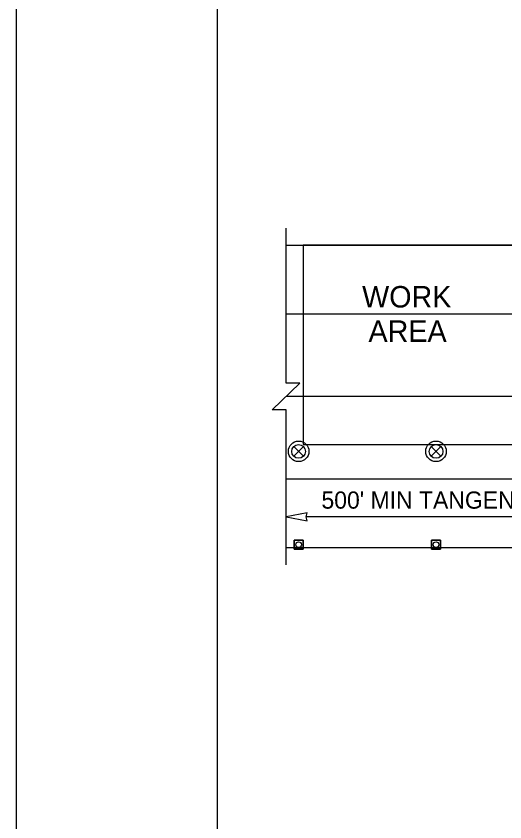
# Model space of a CAD drawing. Extents: x 99999 to 100116, y 99995 to 100013.
# Drawn here: x 100059.062 to 100061.34, y 100005.282 to 100009.035 of the extents above; entities that cross this region are included whole.
import ezdxf

# ---------------------------------------------------------------- set-up
doc = ezdxf.new("R2010")
doc.units = 0
for name, color, linetype in [('RD_MK_LineEdgeYellow', 7, 'Continuous'), ('RD_MK_LineLane', 7, 'Continuous'), ('SH_GI_PlotLimits', 7, 'Continuous'), ('SH_GI_SheetBorder', 7, 'Continuous'), ('TR_WZ_TrafficCone', 7, 'Continuous'), ('TR_WZ_TrafficSafetyDrum', 7, 'Continuous'), ('TR_WZ_WorkAreaLabel', 7, 'Continuous'), ('TR_WZ_WorkZoneDetails', 7, 'Continuous'), ('TR_WZ_WorkZoneTextCurrent', 7, 'Continuous')]:
    doc.layers.add(name, color=color, linetype=linetype)

msp = doc.modelspace()

# ---------------------------------------------------------------- linework, layer by layer
at = {"layer": 'RD_MK_LineEdgeYellow'}
for p, q in [((100060.32, 100007.648), (100062.7119, 100007.648)), ((100060.32, 100006.88), (100067.555, 100006.88))]:
    msp.add_line(p, q, dxfattribs=at)
at = {"layer": 'RD_MK_LineLane'}
msp.add_lwpolyline([(100067.555, 100007.264), (100060.32, 100007.264)], dxfattribs=at)
at = {"layer": 'SH_GI_PlotLimits'}
msp.add_lwpolyline([(100059.0625, 99999.6875), (100076.0625, 99999.6875), (100076.0625, 100010.6875), (100059.0625, 100010.6875)], close=True, dxfattribs=at)
at = {"layer": 'SH_GI_SheetBorder'}
msp.add_line((100060, 100010.375), (100060, 100000), dxfattribs=at)
at = {"layer": 'TR_WZ_TrafficCone'}
for points in [[(100060.3576, 100006.552), (100060.4003, 100006.552), (100060.4003, 100006.5947), (100060.3576, 100006.5947), (100060.3576, 100006.552)], [(100060.3576, 100006.5947), (100060.4003, 100006.5947), (100060.4003, 100006.552), (100060.3576, 100006.552), (100060.3576, 100006.5947)], [(100060.9976, 100006.552), (100061.0403, 100006.552), (100061.0403, 100006.5947), (100060.9976, 100006.5947), (100060.9976, 100006.552)], [(100060.9976, 100006.5947), (100061.0403, 100006.5947), (100061.0403, 100006.552), (100060.9976, 100006.552), (100060.9976, 100006.5947)]]:
    msp.add_lwpolyline(points, dxfattribs=at)
for centre in [(100060.3789, 100006.5734), (100061.0189, 100006.5734)]:
    msp.add_circle(centre, 0.0133, dxfattribs=at)
at = {"layer": 'TR_WZ_TrafficSafetyDrum'}
for p, q in [((100060.3563, 100006.9854), (100060.4015, 100007.0306)), ((100060.4015, 100006.9854), (100060.3563, 100007.0306)), ((100060.9963, 100006.9854), (100061.0415, 100007.0306)), ((100061.0415, 100006.9854), (100060.9963, 100007.0306))]:
    msp.add_line(p, q, dxfattribs=at)
for centre, radius in [((100060.3789, 100007.008), 0.048), ((100060.3789, 100007.008), 0.048), ((100060.3789, 100007.008), 0.032), ((100061.0189, 100007.008), 0.048), ((100061.0189, 100007.008), 0.048), ((100061.0189, 100007.008), 0.032)]:
    msp.add_circle(centre, radius, dxfattribs=at)
at = {"layer": 'TR_WZ_WorkZoneDetails'}
for p, q in [((100060.32, 100007.968), (100062.9559, 100007.968)), ((100061.5748, 100006.7031), (100060.4137, 100006.7031)), ((100060.32, 100006.56), (100067.555, 100006.56))]:
    msp.add_line(p, q, dxfattribs=at)
msp.add_lwpolyline([(100060.32, 100006.48), (100060.32, 100007.2021), (100060.256, 100007.2021), (100060.384, 100007.326), (100060.32, 100007.326), (100060.32, 100008.048)], dxfattribs=at)
for points in [[(100060.4, 100007.968), (100060.4, 100007.04), (100061.6685, 100007.04), (100061.6685, 100007.968)], [(100060.32, 100006.7031), (100060.4183, 100006.6838), (100060.4137, 100006.7031), (100060.4183, 100006.7224)]]:
    msp.add_lwpolyline(points, close=True, dxfattribs=at)

# ---------------------------------------------------------------- texts
at = {"layer": 'TR_WZ_WorkAreaLabel'}
for s, p in [('WORK', (100060.6746, 100007.678)), ('AREA', (100060.7043, 100007.518))]:
    msp.add_text(s, height=0.1, dxfattribs=at).set_placement(p)
at = {"layer": 'TR_WZ_WorkZoneTextCurrent'}
msp.add_text("500' MIN TANGENT", height=0.08, dxfattribs=at).set_placement((100060.4852, 100006.7411))

doc.saveas('drawing.dxf')
